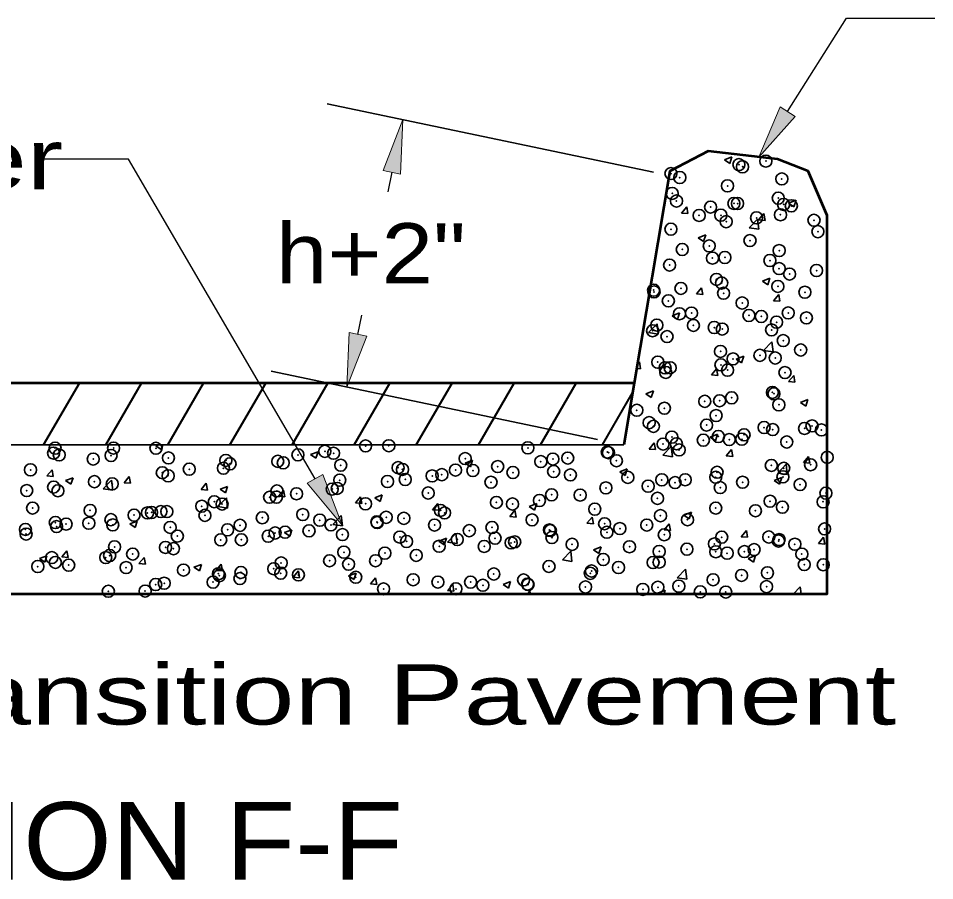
# Model space of a CAD drawing. Extents: x 14 to 49.3, y 28 to 50.
# Drawn here: x 20.615 to 22.745, y 37.196 to 39.2 of the extents above; entities that cross this region are included whole.
import ezdxf

# ---------------------------------------------------------------- set-up
doc = ezdxf.new("R2010")
doc.units = 0
doc.header["$LTSCALE"] = 0.056
doc.header["$PDMODE"] = 32
doc.header["$PDSIZE"] = 0.028
for name, color, linetype, lineweight in [('1', 7, 'Continuous', 35), ('3', 7, 'Continuous', 13), ('6', 7, 'Continuous', 13)]:
    doc.layers.add(name, color=color, linetype=linetype, lineweight=lineweight)

msp = doc.modelspace()

# ---------------------------------------------------------------- hatches: boundary and pattern name
at = {"layer": '1'}
for points in [[(21.50358, 38.83783), (21.46275, 38.84642), (21.50875, 38.9645), (21.50875, 38.9645)], [(21.42483, 38.46117), (21.384, 38.46958), (21.37883, 38.343), (21.37883, 38.343)]]:
    msp.add_hatch(color=256, dxfattribs=at).paths.add_polyline_path(points)
at = {"layer": '3'}
for points in [[(22.42067, 38.97217), (22.3855, 38.99442), (22.33633, 38.87758), (22.33633, 38.87758)], [(21.32275, 38.14008), (21.28675, 38.11917), (21.36767, 38.02158), (21.36767, 38.02158)]]:
    msp.add_hatch(color=256, dxfattribs=at).paths.add_polyline_path(points)

# ---------------------------------------------------------------- linework, layer by layer
at = {"layer": '1'}
for p, q in [((22.09133, 38.84267), (21.33258, 39.00133)), ((22.25617, 38.87108), (22.27367, 38.87783)), ((22.25617, 38.87108), (22.26858, 38.86275)), ((22.26858, 38.86267), (22.27367, 38.87783)), ((22.40533, 38.77042), (22.42283, 38.77717)), ((22.40533, 38.77042), (22.41775, 38.76208)), ((22.41783, 38.76208), (22.42283, 38.77717)), ((22.1565, 38.74733), (22.16858, 38.76167)), ((22.1565, 38.74733), (22.17142, 38.746)), ((22.17142, 38.746), (22.16858, 38.76167)), ((22.33583, 38.73158), (22.34783, 38.746)), ((22.35075, 38.73033), (22.34783, 38.746)), ((22.31375, 38.713), (22.33325, 38.73333)), ((22.31375, 38.713), (22.33325, 38.73333)), ((22.336, 38.70958), (22.33325, 38.73333)), ((22.33583, 38.73158), (22.35075, 38.73033)), ((22.31375, 38.713), (22.336, 38.70958)), ((22.19533, 38.68983), (22.21283, 38.6965)), ((22.19533, 38.68983), (22.20775, 38.68142)), ((22.20775, 38.68142), (22.21283, 38.6965)), ((22.3445, 38.58917), (22.362, 38.59583)), ((22.3445, 38.58917), (22.362, 38.59583)), ((22.357, 38.58075), (22.362, 38.59583)), ((22.19117, 38.55925), (22.20325, 38.57358)), ((22.20617, 38.55792), (22.20325, 38.57358)), ((22.3445, 38.58917), (22.357, 38.58075)), ((22.19117, 38.55925), (22.20617, 38.55792)), ((22.3705, 38.54358), (22.38258, 38.55792)), ((22.38542, 38.54225), (22.38258, 38.55792)), ((22.3705, 38.54358), (22.38542, 38.54225)), ((22.1345, 38.5085), (22.152, 38.51525)), ((22.1345, 38.5085), (22.14692, 38.50017)), ((22.14692, 38.50017), (22.152, 38.51525)), ((22.08017, 38.4695), (22.09958, 38.48975)), ((22.10233, 38.466), (22.09958, 38.48975)), ((22.49375, 38.4885), (22.49525, 38.48908)), ((22.49375, 38.4885), (22.49525, 38.4875)), ((22.08017, 38.4695), (22.10233, 38.466)), ((22.34692, 38.42808), (22.36642, 38.44842)), ((22.36917, 38.42467), (22.36642, 38.44842)), ((22.34692, 38.42808), (22.36917, 38.42467)), ((22.05408, 38.39592), (22.05858, 38.40125)), ((22.0615, 38.38558), (22.05858, 38.40125)), ((22.28367, 38.40783), (22.30117, 38.41458)), ((22.28367, 38.40783), (22.29617, 38.3995)), ((22.29617, 38.3995), (22.30125, 38.41458)), ((21.96142, 38.22125), (21.20267, 38.37983)), ((22.0525, 38.38633), (22.0615, 38.38558)), ((22.22583, 38.37117), (22.23792, 38.38558)), ((22.24083, 38.36992), (22.23792, 38.38558)), ((22.22583, 38.37117), (22.24083, 38.36992)), ((22.40517, 38.3555), (22.41725, 38.36983)), ((22.42017, 38.35417), (22.41725, 38.36983)), ((22.40517, 38.3555), (22.42017, 38.35417)), ((22.07367, 38.32725), (22.09117, 38.33392)), ((22.07367, 38.32725), (22.08608, 38.31883)), ((22.08608, 38.31883), (22.09117, 38.33392)), ((22.43292, 38.30725), (22.45042, 38.31392)), ((22.43292, 38.30725), (22.44533, 38.29883)), ((22.44533, 38.29883), (22.45042, 38.31392)), ((22.22283, 38.22658), (22.24033, 38.23333)), ((22.23533, 38.21817), (22.24042, 38.23333)), ((22.08125, 38.19883), (22.09333, 38.21317)), ((22.09617, 38.1975), (22.09333, 38.21317)), ((22.22283, 38.22658), (22.23533, 38.21817)), ((22.02258, 38.20842), (18.97267, 38.20842)), ((20.935, 38.206), (20.94133, 38.20842)), ((20.935, 38.206), (20.94742, 38.19758)), ((20.94742, 38.19758), (20.951, 38.20842)), ((21.29425, 38.186), (21.31175, 38.19275)), ((21.30667, 38.17758), (21.31175, 38.19267)), ((22.08125, 38.19883), (22.09617, 38.1975)), ((22.11325, 38.18458), (22.13275, 38.20483)), ((22.1355, 38.18108), (22.13275, 38.20483)), ((22.26058, 38.18317), (22.27258, 38.1975)), ((22.2755, 38.18183), (22.27258, 38.1975)), ((21.29425, 38.186), (21.30667, 38.17758)), ((21.6535, 38.166), (21.671, 38.17267)), ((21.6535, 38.166), (21.666, 38.15758)), ((21.666, 38.15758), (21.67108, 38.17267)), ((22.11325, 38.18458), (22.1355, 38.18108)), ((22.26058, 38.18317), (22.2755, 38.18183)), ((22.43992, 38.1675), (22.45192, 38.18183)), ((22.43992, 38.1675), (22.45483, 38.16617)), ((22.45483, 38.16617), (22.45192, 38.18183)), ((20.68142, 38.13633), (20.6935, 38.15067)), ((20.69633, 38.135), (20.6935, 38.15067)), ((22.01283, 38.14592), (22.03033, 38.15267)), ((22.01283, 38.14592), (22.02525, 38.13758)), ((22.02525, 38.13758), (22.03033, 38.15267)), ((22.38008, 38.14317), (22.39958, 38.1635)), ((22.40233, 38.13975), (22.39958, 38.1635)), ((20.68142, 38.13633), (20.69633, 38.135)), ((20.72492, 38.12542), (20.74242, 38.13208)), ((20.72492, 38.12542), (20.73733, 38.117)), ((20.73733, 38.117), (20.74242, 38.13208)), ((20.81233, 38.10658), (20.83183, 38.12683)), ((20.83458, 38.10308), (20.83183, 38.12683)), ((20.86075, 38.12058), (20.87275, 38.135)), ((20.87567, 38.11933), (20.87275, 38.135)), ((22.37208, 38.12592), (22.38958, 38.13267)), ((22.37208, 38.12592), (22.3845, 38.1175)), ((22.38008, 38.14317), (22.40233, 38.13975)), ((22.3845, 38.1175), (22.38958, 38.13267)), ((20.81233, 38.10658), (20.83458, 38.10308)), ((20.86075, 38.12058), (20.87567, 38.11933)), ((21.04008, 38.10492), (21.05208, 38.11925)), ((21.04008, 38.10492), (21.055, 38.10358)), ((21.055, 38.10358), (21.05208, 38.11925)), ((21.08417, 38.10533), (21.10167, 38.11208)), ((21.08417, 38.10533), (21.09667, 38.097)), ((21.09667, 38.097), (21.10167, 38.11208)), ((21.21933, 38.08925), (21.23142, 38.10358)), ((21.23433, 38.08792), (21.23142, 38.10358)), ((21.07917, 38.06517), (21.09867, 38.0855)), ((21.10142, 38.06175), (21.09867, 38.0855)), ((21.21933, 38.08925), (21.23433, 38.08792)), ((21.39867, 38.0735), (21.41075, 38.08792)), ((21.41358, 38.07225), (21.41075, 38.08792)), ((21.4435, 38.08533), (21.461, 38.09208)), ((21.4435, 38.08533), (21.45592, 38.07692)), ((21.45592, 38.07692), (21.461, 38.09208)), ((21.07917, 38.06517), (21.10142, 38.06175)), ((21.39867, 38.0735), (21.41358, 38.07225)), ((21.578, 38.05783), (21.59, 38.07225)), ((21.59292, 38.0565), (21.59008, 38.07225)), ((21.80275, 38.06533), (21.82025, 38.072)), ((21.80275, 38.06533), (21.81517, 38.05692)), ((21.81517, 38.05692), (21.82025, 38.072)), ((21.346, 38.02383), (21.36542, 38.04408)), ((21.36825, 38.02033), (21.3655, 38.04408)), ((21.578, 38.05783), (21.59292, 38.05658)), ((21.75733, 38.04217), (21.76933, 38.0565)), ((21.75733, 38.04217), (21.77225, 38.04083)), ((21.77225, 38.04083), (21.76933, 38.0565)), ((21.93658, 38.0265), (21.94867, 38.04083)), ((21.95158, 38.02517), (21.94867, 38.04083)), ((22.162, 38.04533), (22.17958, 38.052)), ((22.162, 38.04533), (22.1745, 38.03692)), ((22.1745, 38.03692), (22.17958, 38.052)), ((20.87417, 38.02475), (20.89167, 38.03142)), ((20.87417, 38.02475), (20.88658, 38.01633)), ((20.88658, 38.01633), (20.89167, 38.03142)), ((21.346, 38.02383), (21.36825, 38.02033)), ((21.93658, 38.0265), (21.95158, 38.02517)), ((22.11592, 38.01075), (22.128, 38.02517)), ((22.13092, 38.0095), (22.128, 38.02517)), ((21.23342, 38.00467), (21.25092, 38.01142)), ((21.23342, 38.00467), (21.24583, 37.99633)), ((21.24583, 37.99633), (21.25092, 38.01142)), ((21.61283, 37.98242), (21.63225, 38.00275)), ((21.635, 37.979), (21.63225, 38.00267)), ((22.11592, 38.01075), (22.13092, 38.0095)), ((22.29525, 37.99508), (22.30733, 38.0095)), ((22.31017, 37.99375), (22.30733, 38.0095)), ((21.59267, 37.98467), (21.61017, 37.99142)), ((21.59267, 37.98467), (21.60517, 37.97633)), ((21.60517, 37.97625), (21.61025, 37.99142)), ((21.61283, 37.98242), (21.635, 37.979)), ((22.29525, 37.99508), (22.31017, 37.99383)), ((22.47458, 37.97942), (22.48658, 37.99375)), ((22.47458, 37.97942), (22.4895, 37.97808)), ((22.4895, 37.97808), (22.48658, 37.99375)), ((20.71608, 37.94825), (20.72817, 37.96258)), ((20.73108, 37.94692), (20.72817, 37.96258)), ((21.87958, 37.941), (21.89908, 37.96133)), ((21.90183, 37.93758), (21.89908, 37.96133)), ((21.952, 37.96467), (21.9695, 37.97142)), ((21.952, 37.96467), (21.96442, 37.95625)), ((21.96442, 37.95625), (21.9695, 37.97133)), ((20.66408, 37.94408), (20.68158, 37.95083)), ((20.66408, 37.94408), (20.6765, 37.93567)), ((20.6765, 37.93567), (20.68158, 37.95083)), ((20.71608, 37.94825), (20.73108, 37.94692)), ((20.89542, 37.93258), (20.9075, 37.94692)), ((20.89542, 37.93258), (20.91033, 37.93125)), ((20.91033, 37.93125), (20.9075, 37.94692)), ((21.87958, 37.941), (21.90183, 37.93758)), ((22.31125, 37.94467), (22.32875, 37.95133)), ((22.31125, 37.94467), (22.32367, 37.93625)), ((22.32375, 37.93625), (22.32875, 37.95133)), ((21.02333, 37.92408), (21.04083, 37.93075)), ((21.02333, 37.92408), (21.03583, 37.91567)), ((21.03583, 37.91567), (21.04092, 37.93075)), ((21.07475, 37.91683), (21.08675, 37.93125)), ((21.07475, 37.91683), (21.08967, 37.91558)), ((21.08967, 37.91558), (21.08675, 37.93125)), ((21.25408, 37.90117), (21.26608, 37.91558)), ((21.269, 37.89983), (21.26608, 37.9155)), ((21.38267, 37.90408), (21.40017, 37.91075)), ((21.39508, 37.89567), (21.40017, 37.91075)), ((22.14642, 37.89967), (22.16592, 37.91992)), ((22.16867, 37.89617), (22.16592, 37.91992)), ((21.25408, 37.90117), (21.269, 37.89983)), ((21.38267, 37.90408), (21.39508, 37.89567)), ((21.43333, 37.8855), (21.44542, 37.89983)), ((21.44833, 37.88417), (21.44542, 37.89983)), ((21.74192, 37.884), (21.75942, 37.89075)), ((21.75433, 37.87567), (21.75942, 37.89075)), ((22.14642, 37.89967), (22.16867, 37.89617)), ((21.43333, 37.8855), (21.44833, 37.88417)), ((21.61267, 37.86983), (21.62475, 37.88417)), ((21.61267, 37.86983), (21.62758, 37.8685)), ((21.62767, 37.8685), (21.62475, 37.88417)), ((21.74192, 37.884), (21.75433, 37.87567)), ((21.79892, 37.86233), (21.80408, 37.8685)), ((21.80517, 37.86233), (21.80408, 37.8685)), ((22.10125, 37.864), (22.11875, 37.87075)), ((22.11592, 37.86233), (22.11875, 37.87075)), ((22.41717, 37.86233), (22.43267, 37.87858)), ((22.43458, 37.86233), (22.43267, 37.87858)), ((22.10125, 37.864), (22.10367, 37.86233))]:
    msp.add_line(p, q, dxfattribs=at)
at = {"layer": '1', "lineweight": 25}
for p, q in [((21.48317, 38.84208), (21.47375, 38.79708)), ((21.40442, 38.46542), (21.41383, 38.51042))]:
    msp.add_line(p, q, dxfattribs=at)
at = {"layer": '1', "lineweight": 53}
for q in [(18.97467, 38.35233), (22.02258, 38.20842)]:
    msp.add_line((22.04675, 38.35233), q, dxfattribs=at)
at = {"layer": '1', "lineweight": 40}
for p, q in [((20.674, 38.20842), (20.75708, 38.35233)), ((20.81833, 38.20842), (20.90142, 38.35233)), ((20.96267, 38.20842), (21.04583, 38.35233)), ((21.107, 38.20842), (21.19017, 38.35233)), ((21.25142, 38.20842), (21.3345, 38.35233)), ((21.39575, 38.20842), (21.47883, 38.35233)), ((21.54008, 38.20842), (21.62317, 38.35233)), ((21.68442, 38.20842), (21.7675, 38.35233)), ((21.82875, 38.20842), (21.91183, 38.35233)), ((21.97308, 38.20842), (22.04292, 38.32942))]:
    msp.add_line(p, q, dxfattribs=at)
at = {"layer": '1', "lineweight": 13}
for points in [[(21.50358, 38.83783), (21.46275, 38.84642), (21.50875, 38.9645), (21.50875, 38.9645)], [(21.42483, 38.46117), (21.384, 38.46958), (21.37883, 38.343), (21.37883, 38.343)]]:
    msp.add_lwpolyline(points, close=True, dxfattribs=at)
at = {"layer": '1', "lineweight": 53}
msp.add_lwpolyline([(18.95483, 37.86233), (22.49525, 37.86233), (22.49525, 38.74167), (22.45067, 38.8445), (22.37925, 38.87258), (22.21875, 38.89133), (22.12958, 38.8445), (22.04675, 38.35233)], dxfattribs=at)
at = {"layer": '1'}
for p in [(22.28992, 38.85992), (22.29833, 38.85492), (22.3525, 38.86817), (22.132, 38.83917), (22.1525, 38.82992), (22.38967, 38.82667), (22.135, 38.793), (22.26342, 38.81058), (22.14483, 38.77542), (22.27825, 38.76975), (22.28675, 38.76958), (22.38142, 38.782), (22.22417, 38.76133), (22.39375, 38.76742), (22.41175, 38.76417), (22.1975, 38.74183), (22.248, 38.74242), (22.26033, 38.72742), (22.331, 38.73617), (22.38658, 38.74342), (22.46442, 38.73058), (22.132, 38.70983), (22.4735, 38.70417), (22.22092, 38.67092), (22.31567, 38.68342), (22.15833, 38.66275), (22.2285, 38.64267), (22.25733, 38.64417), (22.38358, 38.66017), (22.12892, 38.62658), (22.362, 38.63708), (22.38342, 38.61825), (22.40775, 38.60558), (22.47033, 38.61383), (22.23767, 38.59325), (22.24983, 38.58483), (22.09183, 38.56817), (22.09258, 38.56408), (22.15517, 38.57233), (22.25425, 38.56092), (22.3805, 38.57692), (22.44333, 38.56333), (22.12592, 38.54333), (22.29758, 38.53833), (22.17983, 38.51492), (22.40458, 38.51525), (22.15175, 38.51333), (22.31325, 38.50933), (22.342, 38.507), (22.3775, 38.49375), (22.44675, 38.50367), (22.08942, 38.47375), (22.09908, 38.487), (22.18408, 38.48625), (22.23258, 38.48133), (22.25125, 38.47775), (22.366, 38.47575), (22.12283, 38.46017), (22.393, 38.45083), (22.4335, 38.42908), (22.24725, 38.42583), (22.27625, 38.40842), (22.33883, 38.41667), (22.3745, 38.4105), (22.10142, 38.40083), (22.11833, 38.38758), (22.13008, 38.38792), (22.24817, 38.3945), (22.11983, 38.37692), (22.26358, 38.38225), (22.397, 38.37658), (22.36775, 38.3305), (22.37142, 38.32725), (22.21042, 38.30975), (22.24517, 38.31125), (22.27308, 38.318), (22.38275, 38.30167), (22.05258, 38.289), (22.11675, 38.29367), (22.08142, 38.26017), (22.23692, 38.27667), (22.09108, 38.25167), (22.21483, 38.2545), (22.34833, 38.24883), (22.36842, 38.24408), (22.44258, 38.24683), (22.45983, 38.25267), (22.48175, 38.24325), (22.13408, 38.22658), (22.20725, 38.21942), (22.24208, 38.22808), (22.26758, 38.22092), (22.29683, 38.22175), (22.30192, 38.23192), (20.70042, 38.20092), (20.8365, 38.20108), (20.93508, 38.20058), (21.42225, 38.206), (21.47617, 38.20658), (21.7995, 38.20158), (22.11375, 38.21042), (22.14467, 38.21117), (22.151, 38.19675), (22.401, 38.21525), (20.69708, 38.18942), (20.71025, 38.18508), (20.78925, 38.17558), (20.83058, 38.18383), (20.964, 38.17817), (21.265, 38.18533), (21.32758, 38.19358), (21.34783, 38.189), (21.65375, 38.17658), (21.85758, 38.17567), (21.89208, 38.17792), (21.98392, 38.19175), (21.98683, 38.19042), (22.49517, 38.17958), (21.01242, 38.15208), (21.09167, 38.15425), (21.0975, 38.1725), (21.10708, 38.1645), (21.218, 38.17025), (21.23092, 38.16692), (21.36442, 38.16125), (21.49783, 38.15558), (21.72925, 38.15808), (21.8295, 38.16967), (22.00525, 38.17175), (22.36533, 38.16083), (22.39408, 38.15408), (22.45667, 38.16233), (20.6435, 38.1505), (20.94983, 38.14383), (20.96333, 38.13667), (21.50792, 38.1515), (21.577, 38.13642), (21.59942, 38.13933), (21.63133, 38.15), (21.67167, 38.14892), (21.76475, 38.14433), (21.85942, 38.14667), (21.89825, 38.13867), (22.03167, 38.13308), (22.23617, 38.13325), (22.23908, 38.14483), (22.39233, 38.13425), (20.69725, 38.11058), (20.79192, 38.123), (20.8335, 38.11792), (21.36217, 38.1265), (21.47317, 38.12333), (21.51442, 38.12817), (21.71367, 38.12167), (22.07892, 38.11258), (22.11067, 38.12725), (22.1415, 38.12083), (22.16517, 38.12742), (22.29858, 38.12175), (22.432, 38.11617), (20.63467, 38.10233), (20.70725, 38.10192), (21.21633, 38.1015), (21.26183, 38.09492), (21.34475, 38.10575), (21.3565, 38.10742), (21.56783, 38.09667), (21.85458, 38.0925), (21.921, 38.09183), (21.98083, 38.1085), (22.2465, 38.10925), (22.49217, 38.09633), (21.07058, 38.07642), (21.08867, 38.071), (21.19925, 38.08675), (21.21492, 38.087), (21.42208, 38.07158), (21.72625, 38.07492), (21.76375, 38.07108), (21.82633, 38.07933), (22.10067, 38.08425), (22.36233, 38.07758), (22.48558, 38.07617), (20.64842, 38.06167), (20.78192, 38.05608), (20.91533, 38.05042), (20.92475, 38.05142), (20.94667, 38.0535), (20.96033, 38.05342), (21.04133, 38.06592), (21.27625, 38.04658), (21.59642, 38.05617), (21.60592, 38.05033), (21.95492, 38.05917), (22.236, 38.06158), (22.32833, 38.0555), (22.39092, 38.06375), (20.70117, 38.02808), (20.72617, 38.02442), (20.77892, 38.02642), (20.83042, 38.03467), (20.88408, 38.04525), (21.04883, 38.04475), (21.18225, 38.03917), (21.31575, 38.0335), (21.44858, 38.02958), (21.44917, 38.02783), (21.47008, 38.04017), (21.51117, 38.03783), (21.80908, 38.03417), (21.97783, 38.02525), (22.10767, 38.044), (22.17042, 38.03467), (20.6315, 38.012), (20.70417, 38.01867), (20.83458, 38.0225), (20.96808, 38.01683), (21.1015, 38.01117), (21.13042, 38.02158), (21.21192, 38.00375), (21.235, 38.00558), (21.29075, 38.00883), (21.34175, 38.0225), (21.58258, 38.02225), (21.66333, 38.00917), (21.71608, 38.01658), (21.8495, 38.01092), (21.85158, 38.00925), (21.983, 38.00533), (22.01317, 38.014), (22.07575, 38.02225), (22.48908, 38.01317), (20.63317, 38.00133), (20.98467, 37.9965), (21.08558, 37.98775), (21.13342, 37.98808), (21.196, 37.99633), (21.36842, 37.99992), (21.50192, 37.99425), (21.5175, 37.98408), (21.63533, 37.98867), (21.72317, 37.99167), (21.76875, 37.983), (21.85525, 37.99317), (22.11642, 37.99967), (22.24992, 37.994), (22.35925, 37.99442), (22.382, 37.98508), (22.38333, 37.98842), (20.83883, 37.9715), (20.95725, 37.97017), (20.97558, 37.96733), (21.59333, 37.97292), (21.698, 37.9725), (21.76058, 37.98075), (21.90225, 37.97733), (22.03567, 37.97175), (22.10467, 37.96075), (22.16917, 37.96608), (22.233, 37.97842), (22.30258, 37.96042), (22.32517, 37.96508), (22.41983, 37.97758), (20.69308, 37.9465), (20.81833, 37.94658), (20.82742, 37.95142), (20.88092, 37.95483), (21.33867, 37.93933), (21.37175, 37.95908), (21.44542, 37.93925), (21.46708, 37.95692), (21.54008, 37.95167), (21.97475, 37.94208), (22.23617, 37.96008), (22.26258, 37.95683), (22.43608, 37.95483), (20.66042, 37.92583), (20.70117, 37.93542), (20.73217, 37.929), (20.86558, 37.92333), (20.99908, 37.91767), (21.20883, 37.92058), (21.22592, 37.93408), (21.38283, 37.931), (21.8485, 37.926), (22.01, 37.92358), (22.09042, 37.93508), (22.10467, 37.93608), (22.44192, 37.93025), (22.48608, 37.92992), (21.08017, 37.909), (21.08258, 37.90458), (21.13025, 37.89775), (21.1325, 37.91208), (21.22492, 37.91025), (21.266, 37.90642), (21.39942, 37.90075), (21.72017, 37.90842), (21.94458, 37.91), (21.94742, 37.91542), (22.29608, 37.90517), (22.35625, 37.91117), (20.93433, 37.884), (20.95425, 37.88692), (21.06767, 37.8895), (21.53292, 37.89517), (21.59033, 37.88967), (21.66633, 37.8895), (21.69483, 37.88217), (21.7895, 37.89458), (21.79875, 37.885), (21.79983, 37.88383), (21.93325, 37.87825), (22.10158, 37.87758), (22.15025, 37.88017), (22.22992, 37.89517), (22.35408, 37.879), (20.82433, 37.86825), (20.90983, 37.86875), (21.464, 37.87367), (21.63225, 37.87392), (22.06667, 37.87258), (22.20017, 37.86692), (22.25933, 37.8665)]:
    msp.add_point(p, dxfattribs=at)
at = {"layer": '3', "lineweight": 25}
for points in [[(22.40308, 38.98333), (22.53983, 39.2), (22.74492, 39.2)], [(21.30475, 38.12958), (20.8715, 38.87283), (20.66992, 38.87283)]]:
    msp.add_lwpolyline(points, dxfattribs=at)
at = {"layer": '3'}
for points in [[(22.42067, 38.97217), (22.3855, 38.99442), (22.33633, 38.87758), (22.33633, 38.87758)], [(21.32275, 38.14008), (21.28675, 38.11917), (21.36767, 38.02158), (21.36767, 38.02158)]]:
    msp.add_lwpolyline(points, close=True, dxfattribs=at)
at = {"layer": '6'}
for p, q in [((21.50875, 38.9645), (21.50883, 38.9645)), ((22.1525, 38.82992), (22.15258, 38.82992)), ((22.02258, 38.20842), (22.02267, 38.20842))]:
    msp.add_line(p, q, dxfattribs=at)

# ---------------------------------------------------------------- texts
at = {"layer": '1', "width": 1.15}
msp.add_text('h+2"', height=0.14, dxfattribs=at).set_placement((21.21383, 38.58375))
at = {"layer": '3'}
for s, height, width, p in [('Concrete Shoulder', 0.14, 1.35, (18.61158, 38.80283)), ('Concrete Transition Pavement', 0.14, 1.4, (19.1155, 37.5585)), ('SECTION F-F', 0.18, 1.1, (19.84658, 37.19817))]:
    msp.add_text(s, height=height, dxfattribs=dict(at, width=width)).set_placement(p)

doc.saveas('drawing.dxf')
